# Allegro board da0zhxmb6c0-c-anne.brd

Outline 165.25 x 116 mm; copper layers: TOP, VCC, IN1, IN2, GND, BOTTOM. Coordinates in mm from the lower left corner of the outline.
Outline path: 0,35.15 0,9.05 4,9.05 arc(5.5,7.55) 4,6.05 2.8,6.05 2.8,1 arc(3.09,0.29) 3.8,0 6.81,0 arc(7.5,0.27) 7.81,0.94 arc(10.08,6.09) 15.17,8.47 arc(17.32,9.16) 18.95,10.71 19.1,10.95 arc(19.46,11.28) 19.94,11.4 24.09,11.4 arc(26,12.09) 27.04,13.85 arc(27.38,14.43) 28.02,14.66 30.85,14.66 arc(31.2,14.81) 31.35,15.16 31.35,17.7 arc(31.5,18.05) 31.85,18.2 35.85,18.2 arc(36.2,18.05) 36.35,17.7 36.35,15.16 arc(36.5,14.81) 36.85,14.66 51.32,14.66 arc(52.03,14.37) 52.32,13.66 52.32,13.6 59.8,13.6 arc(60.51,13.89) 60.8,14.6 103.02,14.6 arc(103.73,14.89) 104.02,15.6 104.02,17.4 arc(104.31,18.11) 105.02,18.4 154.5,18.4 arc(155.21,18.69) 155.5,19.4 155.5,28 arc(155.79,28.71) 156.5,29 156.6,29 arc(157.31,29.29) 157.6,30 157.6,78 arc(157.31,78.71) 156.6,79 152,79 arc(151.29,79.29) 151,80 151,89 arc(151.29,89.71) 152,90 165.25,90 165.25,92 161.64,92 arc(161.15,92.4) 161.44,92.96 161.44,112.04 arc(161.15,112.6) 161.64,113 165.25,113 165.25,114.5 135.2,114.5 arc(134.49,114.79) 134.2,115.5 134.2,116 115.3,116 115.3,114.95 arc(115.01,114.24) 114.3,113.95 101,113.95 arc(100.29,114.24) 100,114.95 100,116 86.5,116 arc(85.79,115.71) 85.5,115 85.5,108.5 arc(85.21,107.79) 84.5,107.5 60,107.5 arc(59.29,107.21) 59,106.5 59,104.5 arc(58.71,103.79) 58,103.5 21.7,103.5 arc(20.99,103.79) 20.7,104.5 20.7,105 arc(19.67,107.47) 17.2,108.5 7.7,108.5 arc(6.99,108.21) 6.7,107.5 6.7,106.3 arc(6.11,104.89) 4.7,104.3 3.6,104.3 arc(3.25,104.15) 3.1,103.8 3.1,101.6 arc(2.95,101.25) 2.6,101.1 2.1,101.1 arc(1.75,100.95) 1.6,100.6 1.6,98.85 11.7,98.85 arc(12.2,98.35) 11.7,97.85 11.7,92.85 arc(12.2,92.35) 11.7,91.85 1.6,91.85 1.6,89.25 arc(1.45,88.9) 1.1,88.75 0.9,88.75 0.9,86.75 7.5,86.75 arc(7.75,86.5) 7.5,86.25 7.5,71.75 arc(7.75,71.5) 7.5,71.25 0.9,71.25 0.9,69.25 1.65,69.25 arc(2,69.1) 2.15,68.75 2.15,66.1 9.95,66.1 arc(10.45,66.6) 10.95,66.1 10.95,52.4 arc(10.45,51.9) 9.95,52.4 2.15,52.4 2.15,47.2 12.35,47.2 arc(12.85,46.7) 12.35,46.2 12.35,40.65 arc(12.85,40.15) 12.35,39.65 2.15,39.65 2.15,37.95 2.95,37.95 arc(3.66,37.66) 3.95,36.95 3.95,36.15 arc(3.66,35.44) 2.95,35.15 0,35.15

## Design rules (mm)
constraint set DEFAULT: min track width 0.108
net group W4(5.5)-2B: nets SOC_CLKOUT_0 SOC_CLKOUT_1
net group W25-T12B: nets RING2 SLEEVE
net group DFP-S4(5)W4(5.5)-2B: nets USB30_RX0+ USB30_RX0+_R USB30_RX0- USB30_RX0-_R USB30_TX0+ USB30_TX0+_C USB30_TX0+_R USB30_TX0- USB30_TX0-_C USB30_TX0-_R
net group DFP-S4(5)W4(5.5)-12B: nets PCIE_RXN2_WLAN PCIE_RXP2_WLAN PCIE_TXN2_WLAN PCIE_TXP2_WLAN
net group DFP-S4(5)W4(5.5)-T2B: nets 5V_HSMBCK 5V_HSMBDT HDMI_SCLK HDMI_SDATA PCIE_TXN2_WLAN_C PCIE_TXP2_WLAN_C SDVO_CLK SDVO_DATA SOC_PCIE_COMN SOC_PCIE_COMP
net group DFP-S4(5)W4(5.5)-T12B: nets CLK_PCIE_WLANN CLK_PCIE_WLANP SATA_RCOMP_DN SATA_RCOMP_DP SATA_RXN0_NGFF SATA_RXN0_R SATA_RXP0_NGFF SATA_RXP0_R SATA_TXN0_NGFF SATA_TXN0_R SATA_TXP0_NGFF SATA_TXP0_R TS_USB+ TS_USB+_I2CCL TS_USB- TS_USB-_I2CDA USB_CAR_N USB_CAR_P USB_CR_N USB_CR_P USB_HUB_N USB_HUB_P USBP0+ USBP0+_R USBP0- USBP0-_R USBP1+ USBP1- USBP2+ USBP2- USBP2_CAR_N USBP2_CAR_P USBP3+ USBP3+_R USBP3- USBP3-_R USBP4+ USBP4-
net group DFP-S4.5(4)W5.5(6)-T12B: nets M_A_CLKN0 M_A_CLKP0 M_A_DQSN0 M_A_DQSN1 M_A_DQSN2 M_A_DQSN3 M_A_DQSN4 M_A_DQSN5 M_A_DQSN6 M_A_DQSN7 M_A_DQSP0 M_A_DQSP1 M_A_DQSP2 M_A_DQSP3 M_A_DQSP4 M_A_DQSP5 M_A_DQSP6 M_A_DQSP7 M_B_CLKN0 M_B_CLKP0 M_B_DQSN0 M_B_DQSN1 M_B_DQSN2 M_B_DQSN3 M_B_DQSN4 M_B_DQSN5 M_B_DQSN6 M_B_DQSN7 M_B_DQSP0 M_B_DQSP1 M_B_DQSP2 M_B_DQSP3 M_B_DQSP4 M_B_DQSP5 M_B_DQSP6 M_B_DQSP7
net group DFP-S6(4)W4.5(4)-T2B: nets C_TX0_HDMI+ C_TX0_HDMI- C_TX1_HDMI+ C_TX1_HDMI- C_TX2_HDMI+ C_TX2_HDMI- C_TXC_HDMI+ C_TXC_HDMI- EDP_AUX#_C EDP_AUX_C EDP_TX0#_C EDP_TX0_C EDP_TX1#_C EDP_TX1_C IN_CLK IN_CLK# IN_D0 IN_D0# IN_D1 IN_D1# IN_D2 IN_D2# INT_EDP_AUXN INT_EDP_AUXP INT_EDP_TXN0 INT_EDP_TXN1 INT_EDP_TXP0 INT_EDP_TXP1 SOC_DDI1_RCOMP SOC_DDI1_RCOMP_P SOC_DDIO_RCOMP SOC_DDIO_RCOMP_P
net group W3.5(4.75)-T12B: nets M_A_DM0 M_A_DM1 M_A_DM2 M_A_DM3 M_A_DM4 M_A_DM5 M_A_DM6 M_A_DM7 M_A_DQ0 M_A_DQ1 M_A_DQ2 M_A_DQ3 M_A_DQ4 M_A_DQ5 M_A_DQ6 M_A_DQ7 M_A_DQ8 M_A_DQ9 M_A_DQ10 M_A_DQ11 M_A_DQ12 M_A_DQ13 M_A_DQ14 M_A_DQ15 M_A_DQ16 M_A_DQ17 M_A_DQ18 M_A_DQ19 M_A_DQ20 M_A_DQ21 M_A_DQ22 M_A_DQ23 M_A_DQ24 M_A_DQ25 M_A_DQ26 M_A_DQ27 M_A_DQ28 M_A_DQ29 M_A_DQ30 M_A_DQ31 M_A_DQ32 M_A_DQ33 M_A_DQ34 M_A_DQ35 M_A_DQ36 M_A_DQ37 M_A_DQ38 M_A_DQ39 M_A_DQ40 M_A_DQ41 M_A_DQ42 M_A_DQ43 M_A_DQ44 M_A_DQ45 M_A_DQ46 M_A_DQ47 M_A_DQ48 M_A_DQ49 M_A_DQ50 M_A_DQ51 M_A_DQ52 M_A_DQ53 M_A_DQ54 M_A_DQ55 M_A_DQ56 M_A_DQ57 M_A_DQ58 M_A_DQ59 M_A_DQ60 M_A_DQ61 M_A_DQ62 M_A_DQ63 M_B_DM0 M_B_DM1 M_B_DM2 M_B_DM3 M_B_DM4 M_B_DM5 M_B_DM6 M_B_DM7 M_B_DQ0 M_B_DQ1 M_B_DQ2 M_B_DQ3 M_B_DQ4 M_B_DQ5 M_B_DQ6 M_B_DQ7 M_B_DQ8 M_B_DQ9 M_B_DQ10 M_B_DQ11 M_B_DQ12 M_B_DQ13 M_B_DQ14 M_B_DQ15 M_B_DQ16 M_B_DQ17 M_B_DQ18 M_B_DQ19 M_B_DQ20 M_B_DQ21 M_B_DQ22 M_B_DQ23 M_B_DQ24 M_B_DQ25 M_B_DQ26 M_B_DQ27 M_B_DQ28 M_B_DQ29 M_B_DQ30 M_B_DQ31 M_B_DQ32 M_B_DQ33 M_B_DQ34 M_B_DQ35 M_B_DQ36 M_B_DQ37 M_B_DQ38 M_B_DQ39 M_B_DQ40 M_B_DQ41 M_B_DQ42 M_B_DQ43 M_B_DQ44 M_B_DQ45 M_B_DQ46 M_B_DQ47 M_B_DQ48 M_B_DQ49 M_B_DQ50 M_B_DQ51 M_B_DQ52 M_B_DQ53 M_B_DQ54 M_B_DQ55 M_B_DQ56 M_B_DQ57 M_B_DQ58 M_B_DQ59 M_B_DQ60 M_B_DQ61 M_B_DQ62 M_B_DQ63
net group W4(5.5)-T2B: nets ACZ_BCLK ACZ_RST# ACZ_SDIN ACZ_SDOUT ACZ_SYNC CLK_24M_DEBUG CLK_24M_DEBUG_C CLK_TPM ICLK_ICOMP ICLK_RCOMP LPC_RCOMP PCH_AZ_CODEC_BITCLK PCH_AZ_CODEC_RST# PCH_AZ_CODEC_SDIN0 PCH_AZ_CODEC_SDOUT PCH_AZ_CODEC_SYNC RTC_X1 RTC_X2 SOC_GPIO_RCOMP SOC_PROCHOT# SVID_ALERT#_SOC SVID_CLK_SOC SVID_DATA_SOC XIN XOUT XTAL25_IN XTAL25_OUT
net group W4(5.5)-T12B: nets ACZ_SPKR BEEP_1 BRTC_EXTPAD CLK_24M_KBC CLKRUN# EMMC_CLK EMMC_CLK_R EMMC_CMD EMMC_DATA_0 EMMC_DATA_1 EMMC_DATA_2 EMMC_DATA_3 EMMC_DATA_4 EMMC_DATA_5 EMMC_DATA_6 EMMC_DATA_7 FST_SPI_D0 FST_SPI_D1 I2C_0_SCL I2C_0_SCL_C I2C_0_SDA I2C_0_SDA_C I2C_1_SCL I2C_1_SDA I2C_2_SCL I2C_2_SDA LAD0 LAD0_C LAD1 LAD1_C LAD2 LAD2_C LAD3 LAD3_C LFRAME# LFRAME#_C M_B_DRAMRST# PCBEEP PCBEEP_EC PCH_DISP_ON PCH_DISP_ON_C PCH_DPST_PWM PCH_DPST_PWM_C PCH_EDP_BLON PCH_EDP_BLON_C PLTRST# RSMRST# SCL_TO_EC SCL_TO_EC_R SD_CLK SD_CLK_R SD_CMD SD_CMD_R SD_D0 SD_D1 SD_D2 SD_D3 SD_DATA0_R SD_DATA1_R SD_DATA2_R SD_DATA3_R SDA_TO_EC SDA_TO_EC_R SLP_S4# SMB_SOC_CLK SMB_SOC_DATA SOC_CLKRUN# SOC_PLTRST# SOC_RSMRST# SOC_RTEST# SOC_SERIRQ SOC_SPI_CLK SOC_SPI_CLK_R SOC_SPI_CLK_R1 SOC_SPI_CS# SOC_SPI_CS#_R SOC_SPI_CS#_R1 SOC_SPI_MISO_R SOC_SPI_MISO_R1 SOC_SPI_MOSI_R SOC_SPI_MOSI_R1 SRT_CRST# SUSB# SUSC# TPCLK TPDATA VR_SVID_ALERT# VR_SVID_CLK VR_SVID_DATA
net group W4.5(6)-T12B: nets M_A_A0 M_A_A1 M_A_A2 M_A_A3 M_A_A4 M_A_A5 M_A_A6 M_A_A7 M_A_A8 M_A_A9 M_A_A10 M_A_A11 M_A_A12 M_A_A13 M_A_A14 M_A_A15 M_A_BS0 M_A_BS1 M_A_BS2 M_A_CAS# M_A_CKE0 M_A_CS#0 M_A_ODT0 M_A_RAS# M_A_WE# M_B_A0 M_B_A1 M_B_A2 M_B_A3 M_B_A4 M_B_A5 M_B_A6 M_B_A7 M_B_A8 M_B_A9 M_B_A10 M_B_A11 M_B_A12 M_B_A13 M_B_A14 M_B_A15 M_B_BS0 M_B_BS1 M_B_BS2 M_B_CAS# M_B_CKE0 M_B_CS#0 M_B_ODT0 M_B_RAS# M_B_WE#
net group W5-T2B: nets DMIC_CLK DMIC_CLK_R DMIC_DAT
net group W5-T12B: nets 2.469V 24737_CMPIN 24737_CMPOUT 24737_ILIM 51216PG AC_PROTECT ACIN ACPRESENT BATT_EN# BATT_EN#_R BI_GATE H_PROCHOT# HWPG_1.05V_EC# HWPG_1.35V MAINON N21102302 N21102373 NB670PG NB671EN NB671PG PCH_SUSPWRDANCK PMU_RSMRST# S5_ON SB_ACDC SUSON SUSPWRDANCK_EC SYS_HWPG SYS_SHDN# TEMP_MBAT VCORE_PWRGD VGG_PWRGD VR_READY_VCORE VR_READY_VGG VRON_VCORE VRON_VGG
net group W6.5(8.5)-T12B: nets M_A_DRAMRST#
net group W10-T1B: nets 24737_SRP
net group W10-T12B: nets 24737_ACDET 24737_ACN 24737_ACP 24737_BM# 24737_SRN 51216MODE 51216REFIN 51216S3 51216S5 51216TRIP 51216VDDQSNS +1.8VREF +1.35VSUS +3V_MINI1_VDD +3V_RTC +15V +V_SMDDR_VREF_DIMM +V_SMDDR_VREF_DQ0 +V_SMDDR_VREF_DQ1 COMP_VCORE COMP_VGG D/C# DDR_1P05_PWR DRAM_RCOMP0 DRAM_RCOMP1 FB_VCORE FB_VGG FUSE1_1P05_PWR FUSE3_1P05_PWR FUSE_1P05_PWR ICLK_1P05_PWR ICMNT ISEN1N_VCORE ISEN1N_VGG ISEN1P_VCORE ISEN1P_VGG M_A_VREF_CA M_A_VREF_DQ M_B_VREF_CA M_B_VREF_DQ MAIND MAINON_ON_G MBCLK MBDATA NB670CLK NB670EN NB671FB S5D SET1_VCORE SET1_VGG SET2_VCORE SET2_VGG SET3_VCORE SET3_VGG SETGND_VCORE SETGND_VGG TON_VCORE TON_VGG TSEN_VCORE TSEN_VGG USB_HSIC_RCOMP USBSSIC_1P05_PWR VCC0_SENSEN_R VCC0_SENSEP_R VCC1_SENSEN VCC1_SENSEN_R VCC1_SENSEP VCC1_SENSEP_R VCLK_VCORE VCLK_VGG VDIO_VCORE VDIO_VGG VGG_SENSEN VGG_SENSEN_R VGG_SENSEP VGG_SENSEP_R WRST#
net group W15-T12B: nets HPL HPL-1 HPL_SYS HPR HPR-1 HPR_SYS LINE1-L LINE1-R LINE1-VREFO-L LINE1-VREFO-R MIC2-VREFO RING2_R SLEEVE_R USB_RCOMP
net group W20-T12B: nets 5041_VCC 24737_BST 24737_REGN 24737_VCC 51216VBST 51216VBST_S +3V_LDO +3VPCU_EC BOOT_VCORE BOOT_VGG CCD_PWR DDI_1P15_PWR HDMI_5V NB670BST NB670BST_S NB670ENLDO NB671BST NB671BST_S PVCC_VCORE VCC_VCORE VCCRTC_1 VL
net group W30-T12B: nets 24737_DH 24737_DL 51216DRVH 51216DRVL +5V_HDD CORE_V1P15_PWR LGATE_VCORE LGATE_VGG
net group W35-T12B: nets L_SPK+ L_SPK+_1 L_SPK- L_SPK-_1 R_SPK+ R_SPK+_1 R_SPK- R_SPK-_1
net group W40-T12B: nets +1.15V +5VA BMPD_1P05_PWR
net group W60-T12B: nets +VDDQ_VTT CORE_1P05_PWR V_BLIGHT
net group W80-T12B: nets +LCDVCC
net group W99-T12B: nets 5VUSB_0

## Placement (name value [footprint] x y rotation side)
C1  470p/50v_4  [C0402]  15.97 63.05 90 bottom
C2  0.1u/10v_4  [C0402]  16.98 63.05 90 bottom
C3  0.1u/10v_4  [C0402]  150.1 103.54 270 bottom
C4  0.1u/10v_4  [C0402]  15.62 78.67 0 bottom
C5  0.1u/10v_4  [C0402]  15.62 79.69 0 bottom
C6  0.1u/10v_4  [C0402]  15.62 80.71 0 bottom
C7  0.1u/10v_4  [C0402]  15.62 81.72 0 bottom
C8  0.1u/10v_4  [C0402]  15.62 74.61 0 bottom
C9  0.1u/10v_4  [C0402]  15.62 75.63 0 bottom
C10  0.1u/10v_4  [C0402]  15.62 76.64 0 bottom
C11  0.1u/10v_4  [C0402]  15.62 77.66 0 bottom
C12  chb@1u/6.3v_4  [C0402]  88.34 37.79 270 bottom
C13  1u/6.3v_4  [C0402]  53.08 43.73 90 bottom
C14  100u/6.3v_1206  [C1206]  20.32 62.91 0 bottom
C15  4.7u/10v_6  [C0603]  154.71 108.04 180 bottom
C16  100u/6.3v_1206  [C1206]  151.69 104.95 90 bottom
C17  1u/10v_6  [C0603]  154.29 107.05 0 top
C18  10u/6.3v_6  [C0603]  42.76 36.11 180 bottom
C19  chb@10u/6.3v_6  [C0603]  68.9 36.54 0 bottom
C20  0.1u/10v_4  [C0402]  18.06 59.76 0 bottom
C21  0.1u/10v_4  [C0402]  18.06 60.77 0 bottom
C22  0.1u/10v_4  [C0402]  16.51 50.56 90 top
C23  0_4  [C0402]  10.03 32.86 180 top
C24  100p/50v_4  [C0402]  17.15 49.37 180 bottom
C25  4.7u/6.3v_6  [C0603]  17.53 45.94 0 bottom
C26  10u/6.3v_4  [C0402]  8.43 23.17 0 top
C27  100p/50v_4  [C0402]  15.86 39.44 180 bottom
C28  4.7u/6.3v_6  [C0603]  17.53 44.38 0 bottom
C30  *100p/50v_4  [C0402]  13.66 23.33 270 top
C31  0.1u/10v_4  [C0402]  3.31 22.08 0 top
C32  10u/6.3v_4  [C0402]  3.31 23.04 0 top
C33  *0.1u/10v_4  [C0402]  58.92 88.71 0 bottom
C34  0.1u/10v_4  [C0402]  13.27 21.49 180 top
C35  10u/6.3v_4  [C0402]  14.24 19.95 270 top
C36  10u/6.3v_4  [C0402]  3.31 21.13 0 top
C38  0.1u/10v_4  [C0402]  13.29 19.95 270 top
C39  0.1u/10v_4  [C0402]  66.92 85.5 180 bottom
C40  0.1u/10v_4  [C0402]  66.9 86.55 180 bottom
C41  *0.1u/10v_4  [C0402]  157.85 110.06 180 top
C42  1u/6.3v_4  [C0402]  143.89 98.77 180 top
C43  1u/10v_4  [C0402]  75.69 86.58 180 bottom
C44  1u/6.3v_4  [C0402]  145.67 98.77 0 top
C45  2.2u/6.3v_4  [C0402]  3.31 18.59 180 top
C47  chb@0.047u/10v_4  [C0402]  107.08 43.09 90 top
C48  1u/6.3v_4  [C0402]  56.42 35.65 90 bottom
C49  10u/6.3v_4  [C0402]  13.67 18.62 180 top
C50  *22p/50v_4  [C0402]  15.88 18.65 180 top
C51  *0.1u/10v_4  [C0402]  86.97 90.11 90 bottom
C52  1u/10v_4  [C0402]  3.51 15.99 0 top
C53  0.1u/10v_4  [C0402]  13.41 15.3 90 top
C55  10p/50v_4  [C0402]  15.88 16.81 0 top
C56  10u/6.3v_6  [C0603]  15.16 15.47 180 top
C57  1u/10v_4  [C0402]  3.51 14.85 180 top
C58  10u/6.3v_4  [C0402]  4.83 14.06 90 top
C59  0.1u/10v_4  [C0402]  119.64 86.2 0 bottom
C60  0_4  [C0402]  3.43 13.3 180 top
C61  0.1u/10v_4  [C0402]  10.54 11.5 90 top
C62  10u/6.3v_4  [C0402]  3.86 11.95 270 top
C63  0.1u/10v_4  [C0402]  68.58 93.03 90 bottom
C64  10u/6.3v_4  [C0402]  11.49 11.5 90 top
C65  0.1u/10v_4  [C0402]  6.12 12.22 0 top
C67  10u/6.3v_4  [C0402]  8.63 11.5 90 top
C68  0.1u/10v_4  [C0402]  9.59 11.5 90 top
C69  10u/6.3v_4  [C0402]  6.12 11.27 0 top
C70  0.1u/10v_4  [C0402]  69.6 93.03 90 bottom
C71  1000p/50v_4  [C0402]  68.45 98.9 0 top
C73  *10p/50v_4  [C0402]  68.45 97.88 180 top
C74  1000p/50v_4  [C0402]  65.15 99 180 top
C75  ac@1u/6.3v_4  [C0402]  150.24 99.91 270 top
C76  *1u/10v_4  [C0402]  15.37 31.71 0 top
C78  *10p/50v_4  [C0402]  65.15 97.98 0 top
C79  0.1u/10v_4x  [C0402]  72.54 93.36 270 bottom
C80  0.1u/10v_4x  [C0402]  73.64 93.36 270 bottom
C81  10u/6.3v_4  [C0402]  14.66 12.87 180 top
C83  0.1u/10v_4  [C0402]  14.66 11.91 180 top
C86  0.1u/10v_4  [C0402]  48.01 72.35 180 bottom
C90  1u/6.3v_4  [C0402]  45.76 89.73 180 bottom
C91  tpm@10u/6.3v_6  [C0603]  127.26 75.53 270 bottom
C92  tpm_n@0.1u/10v_4  [C0402]  140.83 76.04 90 bottom
C94  tpm_n@10u/6.3v_6  [C0603]  139.67 75.91 270 bottom
C95  tpm@0.1u/10v_4  [C0402]  128.53 75.4 270 bottom
C97  tpm@0.1u/10v_4  [C0402]  129.29 71.47 90 bottom
C98  tpm@0.1u/10v_4  [C0402]  139.45 70.15 90 bottom
C99  tpm@0.1u/10v_4  [C0402]  140.4 70.15 90 bottom
C100  0.1u/10v_4  [C0402]  132.87 42.22 270 bottom
C101  0.01u/16v_4  [C0402]  100.48 65.54 90 bottom
C104  0.1u/10v_4  [C0402]  130.22 40.5 180 bottom
C108  *hd@100u/6.3v_3528  [C3528]  138.81 65.75 270 bottom
C117  *10p/50v_4  [C0402]  129.57 36.41 270 bottom
C118  0.1u/10v_4  [C0402]  142.98 28.01 90 bottom
C119  hd@0.01u/16v_4  [C0402]  146.58 76.7 0 bottom
C120  hd@0.01u/16v_4  [C0402]  146.58 77.65 0 bottom
C121  10u/6.3v_6  [C0603]  145.75 29.73 180 bottom
C122  hd@0.01u/16v_4  [C0402]  146.58 74.79 0 bottom
C123  hd@0.01u/16v_4  [C0402]  146.58 75.75 0 bottom
C124  0.1u/10v_4  [C0402]  134.34 22 0 top
C125  *0.1u/25v_4  [C0402]  150.6 27.93 270 top
C126  *0.1u/16v_4  [C0402]  149.1 42.38 270 top
C128  1000p/50v_6  [C0603]  35.28 26.84 0 top
C129  1000p/50v_6  [C0603]  35.28 25.06 0 top
C130  1000p/50v_6  [C0603]  35.28 23.41 0 top
C131  1000p/50v_6  [C0603]  35.28 21.63 0 top
C132  *0.1u/10v_4  [C0402]  155.2 92.93 270 top
C133  0.1u/10v_4x  [C0402]  156.21 92.93 270 top
C134  *220p/50v_4  [C0402]  16.13 83.25 90 top
C135  220p/50v_4  [C0402]  14.99 83.88 90 bottom
C138  15p/50v_4  [C0402]  69.2 86.74 0 bottom
C139  15p/50v_4  [C0402]  70.98 86.74 180 bottom
C140  15p/50v_4  [C0402]  72.63 88.13 180 bottom
C141  18p/50v_4  [C0402]  74.41 88.13 0 bottom
C142  0.1u/10v_4  [C0402]  77.85 83.89 180 top
C143  22u/6.3vs_6  [C0603]  93.46 62.03 180 top
C144  22u/6.3vs_6  [C0603]  63.37 91.51 90 top
C145  22u/6.3vs_6  [C0603]  79.16 93.21 0 top
C146  22u/6.3vs_6  [C0603]  59.95 91.46 90 top
C147  22u/6.3vs_6  [C0603]  64.9 91.51 90 top
C148  22u/6.3vs_6  [C0603]  79.19 90.22 0 top
C149  1u/10v_4  [C0402]  65.15 74.64 270 top
C150  0.1u/10v_4  [C0402]  82.91 83.75 0 top
C151  1u/10v_4  [C0402]  71.5 78.8 180 top
C152  1u/10v_4  [C0402]  66.42 76.42 270 top
C153  1u/10v_4  [C0402]  61.32 77.77 90 top
C154  1u/10v_4  [C0402]  71.5 77.82 180 top
C155  1u/10v_4  [C0402]  75.45 81.83 180 top
C156  1u/10v_4  [C0402]  64.01 74.64 270 top
C157  1u/10v_4  [C0402]  55.12 84.55 180 top
C158  1u/10v_4  [C0402]  66.4 86.02 270 top
C159  1u/10v_4  [C0402]  81.75 82.12 0 top
C160  1u/10v_4  [C0402]  77.59 85.18 0 top
C161  1u/10v_4  [C0402]  87.42 80.73 90 top
C162  1u/10v_4  [C0402]  60.05 78.15 90 top
C163  1u/10v_4  [C0402]  75.11 74.62 0 top
C164  1u/10v_4  [C0402]  75.09 79.67 180 top
C165  1u/10v_4  [C0402]  72.01 73.75 0 top
C166  1u/10v_4  [C0402]  71.14 75.45 90 top
C167  1u/10v_4  [C0402]  87.38 80.17 270 bottom
C168  0.1u/10v_4  [C0402]  83.61 81.77 0 top
C169  1u/10v_4  [C0402]  86.41 80.73 90 top
C170  1u/10v_4  [C0402]  84 80.38 90 top
C171  10u/6.3v_6x  [C0603]  157.73 106.74 90 top
C172  1u/10v_4  [C0402]  70.74 71.34 180 top
C173  0.1u/10v_4  [C0402]  78.93 82.17 180 top
C177  1u/10v_4  [C0402]  81.71 84.85 0 top
C178  1u/10v_4  [C0402]  56.92 77.48 180 top
C179  1u/10v_4  [C0402]  57.81 75.96 180 top
C180  1u/10v_4  [C0402]  70.14 74.89 90 top
C182  *0.1u/10v_4  [C0402]  45.98 68.54 180 bottom
C183  1u/10v_4  [C0402]  64.57 78.78 0 top
C188  22u/6.3vs_6  [C0603]  79.16 91.68 0 top
C191  1u/10v_4  [C0402]  67.82 76.42 180 top
C192  1u/10v_4  [C0402]  67.69 72.61 180 top
C193  1u/10v_4  [C0402]  85.08 79.56 90 top
C194  1u/10v_4  [C0402]  60.07 74.54 180 top
C195  1u/10v_4  [C0402]  66.3 73.5 90 top
C196  1u/10v_4  [C0402]  64.42 88.2 90 bottom
C199  1u/10v_4  [C0402]  86.54 76.46 270 top
C200  1u/10v_4  [C0402]  87.72 77.74 270 top
C201  0.1u/50v_6  [C0603]  61.72 92.78 270 bottom
C202  0.01u/25v_4  [C0402]  63.32 93.26 90 bottom
C203  1u/10v_4  [C0402]  63.4 88.2 90 bottom
C204  1u/10v_4  [C0402]  77.83 73.37 90 top
C205  22u/6.3vs_6  [C0603]  95.54 62.28 270 top
C206  1u/10v_4  [C0402]  72.45 70.73 90 top
C207  1u/10v_4  [C0402]  73.36 72.28 270 top
C208  1u/10v_4  [C0402]  67.82 77.43 180 top
C209  1u/10v_4  [C0402]  68.89 74.77 90 top
C211  1u/10v_4  [C0402]  77.21 74.74 0 top
C213  *4.7u/25v_8  [C0805]  59.74 93.08 90 bottom
C214  1u/10v_4  [C0402]  74.42 73.62 180 top
C215  1u/10v_4  [C0402]  76.19 76.06 180 top
C216  1u/10v_4  [C0402]  76.71 71.85 180 top
C217  1u/10v_4  [C0402]  64.9 72.43 270 top
C218  1u/10v_4  [C0402]  72.01 72.73 180 top
C219  1u/10v_4  [C0402]  66.33 88.2 90 bottom
C220  1u/10v_4  [C0402]  76.07 72.74 0 top
C221  22uf/6.3vt_6  [C0603]  58.82 66.67 270 top
C222  4.7uf/6.3v_6  [C0603]  57.02 66.65 270 top
C223  22uf/6.3vt_6  [C0603]  51.83 66.54 270 top
C224  1u/10v_4  [C0402]  68.28 71.47 0 top
C225  0.01u/25v_4  [C0402]  59.99 90.39 90 bottom
C226  0.1u/10v_4  [C0402]  57.12 90.38 270 bottom
C227  1u/10v_4  [C0402]  74.04 70.7 0 top
C228  1u/10v_4  [C0402]  84 68.89 90 top
C229  22u/6.3v_6  [C0603]  77.12 70.07 90 top
C230  22u/6.3v_6  [C0603]  98.16 74.53 270 top
C231  *0.1u/10v_4  [C0402]  58.56 90.38 270 bottom
C232  22u/6.3v_8  [C0805]  66 91.11 180 bottom
C233  2.2u/10v_8  [C0805]  63.41 90.7 270 bottom
C234  1u/10v_4  [C0402]  61.22 66.27 180 top
C235  4.7uf/6.3v_6  [C0603]  58.68 71.85 90 top
C236  4.7uf/6.3v_6  [C0603]  60.07 68.65 0 top
C237  4.7uf/6.3v_6  [C0603]  72.01 68.93 0 top
C238  4.7uf/6.3v_6  [C0603]  57.02 71.85 90 top
C239  22uf/6.3vt_6  [C0603]  48.5 68.08 270 top
C240  *10p/50v_4  [C0402]  128.53 73.24 0 bottom
C241  22uf/6.3vt_6  [C0603]  46.7 71.04 180 top
C242  4.7uf/6.3v_6  [C0603]  68 69.64 90 top
C243  1u/10v_4  [C0402]  64.9 66.77 270 top
C244  1u/10v_4  [C0402]  64.9 68.54 90 top
C245  1u/10v_4  [C0402]  63.12 68.8 180 top
C247  1u/10v_4  [C0402]  95.66 66.3 0 top
C248  1u/10v_4  [C0402]  84.08 64.73 270 top
C249  1u/10v_4  [C0402]  70.23 68.39 90 top
C250  1u/10v_4  [C0402]  75.69 68.67 270 top
C251  1u/10v_4  [C0402]  69.39 70.12 90 top
C252  22u/6.3v_6  [C0603]  89.89 72.93 270 top
C253  22u/6.3v_6  [C0603]  91.16 72.93 270 top
C254  22u/6.3v_6  [C0603]  92.43 72.93 270 top
C255  1u/10v_4  [C0402]  63.12 66.37 180 top
C256  1u/10v_4  [C0402]  92.12 76.8 180 top
C257  22uf/6.3vt_6  [C0603]  98.44 57.4 90 top
C258  gs@0.1u/25v_4  [C0402]  114.43 59.15 0 top
C259  1u/10v_4  [C0402]  74.73 68.67 90 top
C260  1u/10v_4  [C0402]  73.76 68.67 90 top
C261  22u/6.3vs_6  [C0603]  85.68 64.46 270 top
C262  22u/6.3vs_6  [C0603]  75.2 64.1 270 top
C263  *1u/16v_4  [C0402]  71.5 67.27 180 top
C264  *1u/16v_4  [C0402]  73.28 67.27 180 top
C265  22uf/6.3vt_6  [C0603]  99.95 57.37 90 top
C266  22uf/6.3vt_6  [C0603]  94.76 58.67 0 top
C267  22uf/6.3vt_6  [C0603]  94.76 60.19 0 top
C268  1u/10v_4  [C0402]  71.38 65.57 90 top
C269  1u/10v_4  [C0402]  72.39 65.57 90 top
C270  *0.1u/16v_4  [C0402]  153.44 63.11 90 top
C271  22uf/6.3vt_6  [C0603]  73.31 50.59 180 bottom
C272  *0.1u/16v_4  [C0402]  154.05 65.5 270 top
C273  22uf/6.3vt_6  [C0603]  71.97 48.94 0 bottom
C274  0.01u/25v_4  [C0402]  152.02 63.08 90 top
C275  gs@0.1u/25v_4  [C0402]  115.66 52.67 270 top
C278  10u/6.3v_6  [C0603]  151.99 65.5 270 top
C279  0.1u/10v_4  [C0402]  137.8 39.97 270 bottom
C282  0.1u/10v_4  [C0402]  131.7 40.1 270 bottom
C283  0.1u/10v_4  [C0402]  136.15 36.76 270 bottom
C284  0.1u/10v_4  [C0402]  71.63 62.07 270 top
C286  0.1u/10v_4  [C0402]  108.71 39.08 90 bottom
C287  0.1u/10v_4  [C0402]  123.95 35.02 0 top
C288  0.1u/10v_4  [C0402]  142.29 37.68 90 bottom
C289  0.1u/10v_4  [C0402]  141.34 37.68 90 bottom
C290  1u/6.3v_4  [C0402]  123.95 32.98 0 top
C292  0.1u/10v_4  [C0402]  123.95 34 0 top
C294  1u/10v_6  [C0603]  144.07 100.88 180 top
C297  0.1u/10v_4  [C0402]  124.46 28.16 90 top
C314  gs@10u/6.3v_6  [C0603]  109.14 22.82 0 top
C315  em@0.1u/10v_4  [C0402]  116.21 80.99 0 top
C316  0.1u/25v_4  [C0402]  111.63 52.92 90 top
C317  *0.1u/10v_4  [C0402]  48.9 26.63 270 bottom
C318  *1000p/50v_4  [C0402]  49.79 26.63 90 bottom
C319  0.1u/25v_4  [C0402]  109.09 55.08 90 bottom
C320  180p/50v_4  [C0402]  42.8 19.01 180 top
C321  gs@0.1u/10v_4  [C0402]  109.35 25.74 0 top
C322  em@0.1u/10v_4  [C0402]  114.17 77.31 180 top
C323  *33p/50v_4  [C0402]  120.78 21.03 180 top
C324  0.1u/10v_4  [C0402]  48.01 24.48 270 bottom
C325  0.1u/10v_4  [C0402]  46.74 25.19 270 bottom
C326  *22p/50v_4  [C0402]  114.94 29.17 0 top
C327  em@0.1u/10v_4  [C0402]  120.02 76.29 270 top
C328  em@1u/6.3v_4  [C0402]  115.32 78.7 270 top
C329  10p/50v_4  [C0402]  45.59 18.38 270 top
C330  10p/50v_4  [C0402]  46.61 18.38 270 top
C331  em@0.1u/10v_4  [C0402]  119.64 78.45 90 top
C333  0.22u/25v_6  [C0603]  49.15 24.48 270 bottom
C334  em@1u/6.3v_4  [C0402]  121.03 77.94 0 top
C335  *33p/50v_4  [C0402]  120.27 23.89 180 top
C336  em@1u/6.3v_4  [C0402]  117.48 73.24 0 top
C337  em@1u/6.3v_4  [C0402]  119.38 73.75 180 top
C338  em@0.1u/10v_4  [C0402]  116.46 78.7 90 top
C339  em@0.1u/10v_4  [C0402]  116.97 75.02 270 top
C340  em@0.1u/10v_4  [C0402]  115.19 74.89 180 top
C419  0.1u/16v_4  [C0402]  19.79 24.65 180 bottom
C420  4.7u/6.3v_6  [C0603]  19.58 23.46 0 bottom
C423  1u/6.3v_4  [C0402]  30.35 28.67 0 bottom
C425  4.7u/6.3v_6  [C0603]  28.7 30.66 270 bottom
C426  0.1u/16v_4  [C0402]  27.69 30.71 270 bottom
C427  68p/50v_4  [C0402]  26.67 30.71 270 bottom
C438  1u/6.3v_4  [C0402]  21.97 27.27 180 bottom
C573  *0.1u/10v_4  [C0402]  142.01 108.15 270 top
C575  *0.1u/10v_4  [C0402]  140.61 106.16 180 top
C576  *1u/6.3v_4  [C0402]  144.04 104.89 0 top
C594  180p/50v_4  [C0402]  40.39 18.89 180 top
C595  180p/50v_4  [C0402]  153.85 96.87 180 top
C596  180p/50v_4  [C0402]  78.41 93.61 90 bottom
C597  180p/50v_4  [C0402]  158.12 101.44 90 top
C601  *ssd@10u/6.3v_6  [C0603]  153.02 54.53 90 top
C602  *ssd@0.01u/25v_4  [C0402]  154.88 57.51 270 top
C603  10u/6.3v_6  [C0603]  62.71 67.54 0 top
C604  22u/6.3v_6  [C0603]  93.79 72.96 270 top
C694  180p/50v_4  [C0402]  153.85 97.95 180 top
C698  180p/50v_4  [C0402]  70.87 98.52 90 top
C700  180p/50v_4  [C0402]  81.99 93.69 270 bottom
C702  *0.1u/10v_4  [C0402]  107.04 101.97 0 bottom
C703  1u/6.3v_4  [C0402]  70.94 47.73 90 top
C704  1u/6.3v_4  [C0402]  88.42 39.59 90 bottom
C705  1u/6.3v_4  [C0402]  56.37 38.12 0 bottom
C706  1u/6.3v_4  [C0402]  92.99 35.66 180 bottom
C707  1u/6.3v_4  [C0402]  50.39 34.02 0 top
C708  1u/6.3v_4  [C0402]  56.96 33.63 90 top
C709  1u/6.3v_4  [C0402]  59.71 33.14 180 top
C710  10u/6.3v_6  [C0603]  55.34 32.94 90 top
C711  *1u/6.3v_4  [C0402]  106.06 47.41 90 bottom
C712  *1u/6.3v_4  [C0402]  39.17 41.99 270 bottom
C713  1u/6.3v_4  [C0402]  55.88 48.17 90 bottom
C714  1u/6.3v_4  [C0402]  74.24 49.51 90 top
C715  1u/6.3v_4  [C0402]  74.09 42.7 90 top
C716  1u/6.3v_4  [C0402]  74.06 40.67 90 top
C717  1u/6.3v_4  [C0402]  84.34 36.95 180 top
C718  1u/6.3v_4  [C0402]  60.54 35.86 180 bottom
C719  0.1u/16v_4  [C0402]  36.97 41.95 180 bottom
C720  10u/6.3v_6  [C0603]  76.27 36.26 180 top
C721  10u/6.3v_6  [C0603]  38.86 53.39 270 top
C722  10u/6.3v_6  [C0603]  42.61 36.57 180 top
C723  10u/6.3v_6  [C0603]  53.92 52.34 0 bottom
C724  10u/6.3v_6  [C0603]  68.72 36.6 0 top
C725  *1u/6.3v_4  [C0402]  49.31 55.44 180 top
C726  1u/6.3v_4  [C0402]  50.05 55.39 0 bottom
C727  0.1u/16v_4  [C0402]  38.12 47.03 90 top
C728  1u/6.3v_4  [C0402]  70.97 40.22 90 top
C729  1u/6.3v_4  [C0402]  39.12 49.24 90 bottom
C730  1u/6.3v_4  [C0402]  70.92 51.19 270 top
C731  1u/6.3v_4  [C0402]  60.2 36.46 90 top
C732  0.047u/10v_4  [C0402]  39.06 44.4 90 top
C733  0.047u/10v_4  [C0402]  38.12 44.4 90 top
C734  0.047u/10v_4  [C0402]  70.97 44.96 90 top
C735  0.047u/10v_4  [C0402]  71.91 44.81 90 top
C736  1u/6.3v_4  [C0402]  49.08 36.42 0 top
C737  1u/6.3v_4  [C0402]  39.17 41.23 90 top
C738  1u/6.3v_4  [C0402]  39.17 49.05 90 top
C739  1u/6.3v_4  [C0402]  39.14 51.06 90 top
C740  1u/6.3v_4  [C0402]  53.65 54.78 180 bottom
C741  1u/6.3v_4  [C0402]  53.65 53.89 180 bottom
C742  1u/6.3v_4  [C0402]  39.12 51.15 90 bottom
C743  1u/6.3v_4  [C0402]  49.16 36.49 0 bottom
C744  1u/6.3v_4  [C0402]  39.11 47.03 270 bottom
C745  0.047u/10v_4  [C0402]  39.11 47.03 270 top
C746  0.047u/10v_4  [C0402]  53.17 47.56 270 bottom
C747  0.047u/10v_4  [C0402]  70.99 44.45 270 bottom
C748  0.047u/10v_4  [C0402]  71.61 46.5 180 top
C749  0.1u/10v_4  [C0402]  57 47 270 top
C750  0.2p/50v_4  [C0402]  56.44 48.98 180 top
C751  chb@1u/6.3v_4  [C0402]  95.82 55.39 180 top
C752  chb@1u/6.3v_4  [C0402]  98.44 55.66 0 bottom
C753  chb@1u/6.3v_4  [C0402]  95.71 55.63 180 bottom
C754  chb@1u/6.3v_4  [C0402]  94.08 55.4 0 top
C755  chb@1u/6.3v_4  [C0402]  106.02 39.83 90 top
C756  chb@1u/6.3v_4  [C0402]  106.04 40.27 90 bottom
C757  chb@1u/6.3v_4  [C0402]  106.51 41.5 180 bottom
C758  chb@1u/6.3v_4  [C0402]  74.09 39.66 90 bottom
C759  chb@1u/6.3v_4  [C0402]  88.63 51.61 180 bottom
C760  chb@1u/6.3v_4  [C0402]  97.67 55.37 180 top
C761  chb@1u/6.3v_4  [C0402]  88.21 50.02 270 bottom
C762  chb@1u/6.3v_4  [C0402]  104.68 55.47 180 top
C763  22uf/6.3v_6  [C0603]  108.13 37.54 0 bottom
C764  chb@0.047u/10v_4  [C0402]  74.12 42.78 90 bottom
C765  chb@0.047u/10v_4  [C0402]  105.99 43.01 90 bottom
C766  chb@0.047u/10v_4  [C0402]  106.04 43.08 90 top
C767  chb@10u/6.3v_6  [C0603]  103.69 36.16 180 bottom
C768  chb@10u/6.3v_6  [C0603]  106.4 37.23 270 top
C769  chb@1u/6.3v_4  [C0402]  96.38 35.74 0 bottom
C770  chb@10u/6.3v_6  [C0603]  71.98 49.47 90 top
C771  chb@10u/6.3v_6  [C0603]  73.89 37.53 270 bottom
C772  chb@10u/6.3v_6  [C0603]  108.13 36.18 0 bottom
C773  chb@0.047u/10v_4  [C0402]  92.05 46.59 270 bottom
C774  chb@0.047u/10v_4  [C0402]  74.27 47.07 270 top
C775  chb@0.047u/10v_4  [C0402]  105.99 45.65 270 top
C776  chb@0.047u/10v_4  [C0402]  106.07 45.65 270 bottom
C777  chb@1u/6.3v_4  [C0402]  59.75 34.13 180 top
C778  chb@1u/6.3v_4  [C0402]  59.72 35.12 180 top
C779  chb@1u/6.3v_4  [C0402]  88.73 42.87 180 top
C780  chb@1u/6.3v_4  [C0402]  87.4 33.9 90 top
C781  chb@1u/6.3v_4  [C0402]  91.6 33.66 90 top
C782  chb@10u/6.3v_6  [C0603]  89.41 33.72 0 top
C783  chb@1u/6.3v_4  [C0402]  93.41 33.66 90 top
C784  chb@1u/6.3v_4  [C0402]  94.78 33.68 90 top
C785  chb@1u/6.3v_4  [C0402]  91.97 50.53 270 bottom
C786  chb@1u/6.3v_4  [C0402]  97.38 35.36 90 top
C787  chb@1u/6.3v_4  [C0402]  85.31 36.82 0 bottom
C788  chb@1u/6.3v_4  [C0402]  74.34 46.92 270 bottom
C789  chb@1u/6.3v_4  [C0402]  74.34 48.69 270 bottom
C790  chb@1u/6.3v_4  [C0402]  70.97 42.1 90 bottom
C791  chb@1u/6.3v_4  [C0402]  56.84 49.28 270 bottom
C792  chb@1u/6.3v_4  [C0402]  93.98 55.62 0 bottom
C793  chb@0.1u/10v_4  [C0402]  91.07 48.31 270 bottom
C794  chb@0.2p/50v_4  [C0402]  88.51 47.91 270 bottom
C795  chb@0.1u/16v_4  [C0402]  108.72 45.18 0 bottom
C798  hub@10u/6.3v_4  [C0402]  30.99 68.93 0 bottom
C799  hub@0.1u/16v_4  [C0402]  32.26 61.43 0 top
C800  hub@0.1u/16v_4  [C0402]  28.14 61.28 90 top
C801  hub@1u/6.3v_4  [C0402]  30.13 61.28 90 top
C802  hub@1u/6.3v_4  [C0402]  29.13 61.28 90 top
C803  hub@0.1u/16v_4  [C0402]  30.99 67.91 0 bottom
C804  hub@0.1u/16v_4  [C0402]  27.15 61.28 90 top
C805  hub@0.1u/16v_4  [C0402]  23.88 67.78 0 bottom
C806  hub@22p/50v_4  [C0402]  28.2 59.27 0 bottom
C807  hub@22p/50v_4  [C0402]  29.97 59.27 180 bottom
C808  hub@1u/6.3v_4  [C0402]  23.88 61.69 180 bottom
C812  0.1u/10v_4x  [C0402]  71.55 93.03 270 bottom
C813  0.1u/10v_4x  [C0402]  70.66 93.03 270 bottom
C814  *2.7p/50v_4  [C0402]  18.76 21.24 270 top
C815  *2.7p/50v_4  [C0402]  19.92 21.25 270 bottom
C816  *2.7p/50v_4  [C0402]  19.18 26.1 180 bottom
C817  *2.7p/50v_4  [C0402]  19.6 31.97 180 bottom
C818  *2.7p/50v_4  [C0402]  19.6 30 180 bottom
C819  *2.7p/50v_4  [C0402]  19.78 21.24 270 top
C828  180p/50v_4  [C0402]  109.2 34.59 90 bottom
C829  m2_ssd@0.01u/16v_2  [C0201]  146.2 75.75 180 top
C830  m2_ssd@0.01u/16v_2  [C0201]  146.2 74.79 180 top
C831  m2_ssd@0.01u/16v_2  [C0201]  145.95 76.7 180 top
C832  m2_ssd@0.01u/16v_2  [C0201]  145.95 77.65 180 top
C839  *1000p/50v_4  [C0402]  59.54 95.67 0 top
C840  *0.1u/10v_4  [C0402]  57.3 99.99 0 top
C841  *1u/6.3v_4  [C0402]  57.3 98.97 0 top
C842  4.7u/10v_6  [C0603]  19.05 57.24 90 bottom
C859  *1u/6.3v_4  [C0402]  139.63 52.7 90 top
C860  *10u/6.3v_4  [C0402]  140.88 56.37 270 top
C861  0.1u/10v_4  [C0402]  109.6 50.13 0 top
C862  m2_ssd@0.1u/16v_4  [C0402]  153.93 57.51 270 top
C863  m2_ssd@10u/6.3v_6  [C0603]  154.51 54.56 90 top
C864  *1000p/50v_4  [C0402]  50.29 82.13 90 top
C865  *1000p/50v_4  [C0402]  147.59 53.51 270 top
C866  *1000p/50v_4  [C0402]  30.36 46.79 90 top
C867  *1000p/50v_4  [C0402]  27.43 59.15 0 top
C868  *1000p/50v_4  [C0402]  15.38 21.32 180 top
C869  *1000p/50v_4  [C0402]  48.98 60.56 180 top
C870  *1000p/50v_4  [C0402]  109.35 54.71 90 top
C871  *1000p/50v_4  [C0402]  73.28 35.52 270 top
C872  *1000p/50v_4  [C0402]  71.63 35.52 270 top
C873  *10p/50v_4  [C0402]  17.02 15.46 90 top
C874  hub@1u/6.3v_4  [C0402]  23.5 27.9 270 top
C875  0.1u/10v_4  [C0402]  116.51 111.65 90 bottom
C876  0.1u/10v_4  [C0402]  131.57 59.99 0 top
C877  0.1u/25v_4  [C0402]  111.1 35.35 270 top
C878  0.1u/25v_4  [C0402]  87.35 21.48 180 top
C879  22u/6.3v_6  [C0603]  3.79 24.25 0 top
C880  10u/6.3v_4  [C0402]  6.78 9.95 90 top
CN1  usb3.0 conn  [USB-53065-00902-001-9P-SMT]  4.5 59.25 90 bottom
CN2  hdmi conn  [HDMI-80103-1121-19P-LDV-SMT]  2.7 79 90 bottom
CN3  usb_conn  [AF712L-A2G1T-12P-L-SMT]  148.9 98.5 180 bottom
CN5  ngff@wlan_ngff conn(type 2230)  [NGFF-51749-0750P-105-75P-KE]  159.8 102.5 270 bottom
CN6  combojack_2sj3080-003111f  [PHJK-2SJ3080-088111F-6P]  7.55 43.5 90 bottom
CN7  rtc_socket  [ML1220-SMT]  131 107.5 135 top
CN9  hd@hdd conn  [SATA-C166FQ-12208-L-22P-R]  155.4 57.8 270 bottom
CN10  7300l40-100000-g4  [LVDS-107K40-100011-G2-40P-L]  71 97.7 0 bottom
CN11  kb_conn  [50584-0280N-V01-28P-L]  120.73 28.5 180 bottom
CN12  tp_cn  [88513-0801-8P-L]  46.6 21.9 180 bottom
CN13  power conn  [50281-0040N-001-4P-L]  33.85 20.23 180 bottom
CN16  sd-card  [SDCARD-156-2001902600-11P-SMT]  15.4 22 90 bottom
CN18  m2_ssd@ssd_ngff conn  [NGFF-APCI0018-P002A-75P-KB-SMT]  149.28 62 270 bottom
D2  5v/30v/0.2p_4  [C0402]  14.99 56.3 90 bottom
D3  5v/30v/0.2p_4  [C0402]  14.99 58.08 270 bottom
D5  *vport_6  [R0603]  154.69 108.55 0 top
D7  rb500v-40  [DSM]  18.04 35.91 90 top
D8  rb500v-40  [DSM]  19.81 35.91 90 top
D9  bas316  [DSM]  22.99 22.06 270 top
D10  *bas316  [DSM]  24.77 22.06 270 top
D11  *az5125-01j  [R0402]  14.86 83.25 90 top
D12  *vport_6  [R0603]  155.47 101.34 180 top
D13  rb500v-40  [DSM]  20.19 82.23 0 bottom
D14  rb500v-40  [DSM]  20.19 84.14 0 bottom
D15  rb500v-40  [DSM]  35.56 28.54 0 bottom
D16  sdmk0340l-7-f  [DSMV]  121.21 34.28 90 top
D17  bat54c  [SOT323_213-2_1-1_3-2N7002W]  144.27 102.71 0 top
D18  *rb500v-40  [DSM]  133.73 56.61 0 top
D19  *rb500v-40  [DSM]  133.73 50.89 0 top
D20  rb500v-40  [DSM]  133.73 52.8 0 top
D21  *rb500v-40  [DSM]  133.73 54.7 0 top
D22  em@rb500v-40  [DSM]  105.26 77.25 0 bottom
D23  5v/30v/0.2p_4  [C0402]  14.99 59.86 90 bottom
D24  5v/30v/0.2p_4  [C0402]  14.99 61.64 270 bottom
D25  5v/30v/0.2p_4  [C0402]  14.99 52.88 90 bottom
D26  5v/30v/0.2p_4  [C0402]  14.99 54.59 270 bottom
D27  5v/30v/0.2p_4  [C0402]  15.5 48.86 90 top
D28  5v/30v/0.2p_4  [C0402]  6.99 36.54 180 bottom
D29  *5v/0.2p_4  [C0402]  142.01 106.37 270 top
D30  *5v/0.2p_4  [C0402]  140.61 107.31 0 top
D42  *az5725  [C0402]  109.86 33.24 0 bottom
D43  5v/30v/0.2p_4  [C0402]  149.23 39.59 270 bottom
D44  *5v/30v/0.2p_4  [C0402]  78.84 73.37 270 top
G1  *short_ pad1  [R0603]  144.4 97.37 180 top
HOLE1  *h-o158x118d158x118n  [H-O158X118D158X118N]  9.71 106 0 top
HOLE2  *h-c276d110p2  [H-C276D110P2]  17.2 105 0 top
HOLE3  *h-c276d110p2  [H-C276D110P2]  32 100.8 0 top
HOLE4  *h-c142x118d142x118n  [H-C142X118D142X118N]  40 100.8 0 top
HOLE5  *spad-zxx-5  [SPAD-ZXX-5]  17.2 105 0 top
HOLE6  *h-zxx-6  [H-ZXX-6]  92 112 0 top
HOLE7  *h-tc276ic276bc315d110p2  [H-TC276IC276BC315D110P2]  148 112 0 top
HOLE8  *spad-s354np  [SPAD-S354NP]  148 111.5 180 top
HOLE9  *h-c118d118n  [H-C118D118N]  155 112 0 top
HOLE10  *h-zxx-2  [H-ZXX-2]  16.5 69 0 top
HOLE11  *h-zxx-1  [H-ZXX-1]  33.84 83.66 90 top
HOLE12  *h-zxx-13  [H-ZXX-13]  104.55 60.78 0 top
HOLE13  *h-zhx-1  [H-ZHX-1]  154.13 32.85 0 top
HOLE14  *h-tc276ic197bc315d142x134p2  [H-TC276IC197BC315D142X134P2]  23 15 0 top
HOLE15  *spad-c315  [SPAD-C315]  54.4 17.7 0 top
HOLE16  *spad-zhx-2  [SPAD-ZHX-2]  55.88 17.78 0 bottom
HOLE17  *spad-c315  [SPAD-C315]  137 82.73 180 bottom
HOLE18  *spad-c315  [SPAD-C315]  137 82.73 0 top
JP1  *short_3720  [SHORT3720]  119.2 94.4 270 bottom
JP2  *short_3720  [SHORT3720]  99.54 94.68 90 bottom
JP3  *short_3720  [SHORT3720]  99.47 109.67 90 bottom
JP5  *short_3720  [SHORT3720]  124.84 94.45 90 bottom
JP7  *short_3720  [SHORT3720]  140.21 110.15 0 bottom
JP8  *short_3720  [SHORT3720]  36.4 34.97 270 bottom
JP10  *short_3720  [SHORT3720]  129.92 98.97 90 bottom
JP11  *short_3720  [SHORT3720]  121.92 110.23 90 bottom
JP12  *short_3720  [SHORT3720]  26.54 80.74 0 bottom
L2  0_6  [R0603]  15.62 49.17 90 bottom
L3  0_6  [R0603]  15.62 41.3 270 bottom
L4  hcb2012kf220t60/6a/22ohm_8  [R0805]  10.23 27.58 0 top
L5  80ohm_100mhz  [R0402]  16.51 48.86 270 top
L6  80ohm_100mhz  [R0402]  6.99 35.02 180 top
L7  0_6  [R0603]  8.56 9.7 180 top
L8  hcb1608kf-601t20(600,2a)  [R0603]  11.58 13.02 0 top
L9  blm15ag121sn1d(120,500ma)_4  [R0402]  130.22 39.54 180 bottom
L10  blm15ag121sn1d(120,500ma)_4  [R0402]  142.95 26.69 0 bottom
L11  blm15ag121sn1d(120,500ma)_4  [R0402]  142.04 28.03 90 bottom
LED2  led_amber/blue  [LEDLTST-S326KGJRKT-3P-SMT]  4.7 3 90 top
MR1  och1691wad  [SOT23_123-2_8-1_9]  156 104.5 270 top
MR3  *hgdedm013a  [SENSOR-1_3X0_9-5-4P]  141.5 104.5 0 top
NOREF  -  []  27.23 38.65 0 top
NOREF#2  -  [unnamed#2]  9.18 7.42 0 top
NOREF#3  -  [unnamed#2]  148.98 21.92 0 top
NOREF#4  -  []  56.01 -19.72 0 top
NOREF#5  -  [unnamed#2]  11.75 88.31 0 top
NOREF#6  -  []  5.21 -61.88 0 top
NOREF#7  -  []  56.95 27.12 0 top
NOREF#8  -  []  103.43 72.96 180 bottom
NOREF#9  -  []  48.52 97.37 180 bottom
NOREF#10  -  [unnamed#2]  9.18 7.42 180 bottom
NOREF#11  -  [unnamed#2]  12.71 88.44 180 bottom
NOREF#12  -  [unnamed#2]  148.98 21.92 180 bottom
PC1  2200p/50v_6  [C0603]  7.88 102.38 90 bottom
PC2  22u/6.3v_6  [C0603]  103.53 92.37 90 bottom
PC3  22u/6.3v_6  [C0603]  105.54 92.93 180 bottom
PC4  22u/6.3v_6  [C0603]  99.54 98.21 270 bottom
PC5  0.1u/50v_6  [C0603]  6.48 102.38 90 bottom
PC6  10u/10v_8  [C0805]  112 95.44 90 bottom
PC7  10u/10v_8  [C0805]  113.93 95.44 90 bottom
PC8  10u/10v_8  [C0805]  115.86 95.44 90 bottom
PC9  *220u/2.5v_3528  [C3528]  95.66 97.07 270 bottom
PC10  0.1u/50v_6  [C0603]  16.33 90.62 270 top
PC11  2.2u/6.3v_6  [C0603]  115.44 97.75 180 bottom
PC12  22u/6.3v_6  [C0603]  101.07 98.21 270 bottom
PC13  22u/6.3v_6  [C0603]  102.16 92.37 90 bottom
PC14  2.2u/6.3v_6  [C0603]  118.39 100.42 180 bottom
PC15  22u/6.3v_6  [C0603]  99.98 102.59 0 bottom
PC16  22u/6.3v_6  [C0603]  99.98 106.72 0 bottom
PC17  22u/6.3v_6  [C0603]  99.98 105.32 0 bottom
PC18  1u/10v_4  [C0402]  117.98 101.56 180 bottom
PC19  4.7u/10v_6  [C0603]  118.42 102.73 180 bottom
PC20  0.1u/50v_6  [C0603]  119.76 42.48 0 bottom
PC21  10u/6.3v_6  [C0603]  118.4 104.1 180 bottom
PC22  10u/6.3v_6  [C0603]  116.43 106.32 270 bottom
PC23  10u/6.3v_6  [C0603]  118.4 105.48 180 bottom
PC24  0.47u/25v_6  [C0603]  46.43 63.8 0 bottom
PC25  22u/6.3v_8  [C0805]  52.96 81.37 270 bottom
PC26  22u/6.3v_6  [C0603]  123.57 88.79 0 bottom
PC27  22u/6.3v_6  [C0603]  123.57 90.16 0 bottom
PC28  22u/6.3v_6  [C0603]  123.57 87.42 0 bottom
PC29  0.1u/10v_4  [C0402]  46.31 82.92 180 bottom
PC30  0.1u/10v_4  [C0402]  123.67 85.89 0 bottom
PC31  22u/6.3v_6  [C0603]  123.57 91.51 0 bottom
PC32  0.1u/50v_6  [C0603]  138.07 93.3 0 top
PC33  10u/6.3v_6  [C0603]  138.18 93.89 0 bottom
PC34  *0.1u/10v_4  [C0402]  45.21 63.08 180 top
PC35  *0.1u/10v_4  [C0402]  137.26 92.73 180 bottom
PC37  *0.1u/10v_4  [C0402]  46.1 65.24 180 bottom
PC39  22u/6.3v_8  [C0805]  54.87 81.37 270 bottom
PC40  0.47u/6.3v_4  [C0402]  43.59 61.44 90 bottom
PC41  0.1u/25v_4  [C0402]  42.27 70.27 270 bottom
PC43  100p/50v_4  [C0402]  42.31 61.09 90 bottom
PC44  330u/2v_7343  [CC7343]  49.53 81.12 90 bottom
PC45  0.1u/25v_4  [C0402]  134.06 98.11 180 top
PC46  0.1u/25v_4  [C0402]  134.04 99 0 top
PC47  10u/25v_8  [C0805]  134.47 100.07 180 bottom
PC48  390p/50v_4  [C0402]  43.78 57.94 0 top
PC49  *150u/6.3v_3528  [C3528]  125.5 111.09 270 bottom
PC50  2.2u/6.3v_6  [C0603]  39.98 60.65 270 bottom
PC51  1u/6.3v_4  [C0402]  130.56 94.96 90 bottom
PC52  *0.1u/10v_4  [C0402]  130.18 96.26 180 top
PC53  0.1u/25v_4  [C0402]  130.2 93.18 180 bottom
PC54  0.1u/10v_4  [C0402]  34.29 65.37 180 bottom
PC55  0.1u/10v_4  [C0402]  121.19 101.44 0 bottom
PC56  0.1u/25v_4  [C0402]  34.24 68.39 180 bottom
PC57  22u/6.3v_6  [C0603]  121.54 103.98 0 bottom
PC58  22u/6.3v_6  [C0603]  121.53 102.6 0 bottom
PC59  330u/2v_7343  [CC7343]  113.92 61.81 270 bottom
PC60  0.1u/10v_4  [C0402]  35.61 59.05 90 bottom
PC61  22u/6.3v_6  [C0603]  121.54 107.13 0 bottom
PC62  22u/6.3v_6  [C0603]  121.54 105.55 0 bottom
PC63  10u/25v_8  [C0805]  134.41 61.05 90 bottom
PC64  10u/25v_8  [C0805]  31.37 74.13 270 bottom
PC65  2200p/50v_4  [C0402]  136.81 60.77 90 bottom
PC66  0.1u/25v_4  [C0402]  29.97 74.39 270 bottom
PC67  0.1u/25v_4x  [C0402]  130.63 109.26 90 bottom
PC68  0.1u/25v_4  [C0402]  120.13 57.08 270 top
PC69  1u/6.3v_4  [C0402]  133.02 109.26 90 bottom
PC70  0.47u/25v_6  [C0603]  118.11 52.56 180 top
PC71  *0.1u/10v_4  [C0402]  116.69 52.56 0 bottom
PC72  0.1u/10v_4  [C0402]  127.37 53.29 0 bottom
PC73  *0.1u/10v_4  [C0402]  136.16 109.84 0 bottom
PC74  2200p/50v_4  [C0402]  147.45 105.12 270 bottom
PC75  15u/25v_7343  [CC7343]  23.75 76.42 180 bottom
PC76  *0.1u/10v_4  [C0402]  118.49 49.49 0 top
PC77  10u/25v_8  [C0805]  145.92 105.37 90 bottom
PC78  0.1u/25v_4  [C0402]  98.56 24.65 270 bottom
PC79  0.1u/25v_4  [C0402]  99.52 24.65 270 bottom
PC80  0.1u/25v_4  [C0402]  99.08 25.97 0 bottom
PC81  *680p/50v_6  [C0603]  90.84 26.58 0 top
PC82  *10u/6.3v_6  [C0603]  35.97 50.99 180 bottom
PC83  68p/50v_4  [C0402]  120.52 48.22 90 bottom
PC84  1u/16v_6  [C0603]  93.52 26.58 180 top
PC85  0.1u/10v_4  [C0402]  35.54 46.41 0 bottom
PC86  10u/6.3v_6  [C0603]  35.97 49.6 180 bottom
PC87  0.22u/10v_4  [C0402]  35.54 48.31 0 bottom
PC88  15u/25v_7343  [CC7343]  140.46 103.52 270 bottom
PC89  390p/50v_4  [C0402]  122.43 46.44 270 bottom
PC90  0.1u/10v_4  [C0402]  34.19 46.68 90 bottom
PC91  10u/25v_8  [C0805]  60.2 29.05 270 bottom
PC92  10u/25v_8  [C0805]  76.33 29.17 270 bottom
PC93  0.01u/25v_4  [C0402]  96.78 29.68 90 bottom
PC94  10u/25v_8  [C0805]  97.06 23.26 270 bottom
PC95  2200p/50v_6  [C0603]  95.57 22.38 90 bottom
PC96  47n/50v_6  [C0603]  92.07 23.16 180 top
PC97  0.01u/25v_4  [C0402]  31.27 46.68 90 bottom
PC99  10u/25v_8  [C0805]  137.19 106.06 90 bottom
PC100  100p/50v_4  [C0402]  103.03 24.09 180 top
PC101  *0.1u/10v_4  [C0402]  31.88 53.69 270 top
PC102  *0.1u/10v_4  [C0402]  30.74 53.69 270 top
PC103  0.47u/25v_6  [C0603]  95.12 19.78 180 top
PC104  0.1u/50v_6  [C0603]  97.92 19.78 0 top
PC105  0.1u/25v_4  [C0402]  28.54 49.73 90 bottom
PC106  0.1u/25v_4  [C0402]  20.02 53.87 270 bottom
PC107  1u/6.3v_4  [C0402]  29.23 47.86 90 bottom
PC108  0.1u/50v_6  [C0603]  97.92 18 180 top
PC109  0.1u/50v_6  [C0603]  95.12 18 0 top
PC110  2200p/50v_6  [C0603]  78.11 29.05 90 bottom
PC111  2200p/50v_4  [C0402]  24.54 52.37 0 bottom
PC112  10u/25v_8  [C0805]  25.32 48.94 180 bottom
PC114  2.2u/6.3v_6  [C0603]  112.9 100.17 270 top
PC115  0.1u/50v_6  [C0603]  12.19 102.38 90 bottom
PC116  2.2u/6.3v_6  [C0603]  114.43 100.17 270 top
PC117  0.1u/50v_6  [C0603]  119.76 37.11 0 bottom
PC118  22u/6.3v_6  [C0603]  99.98 103.95 0 bottom
PC119  22u/6.3v_6  [C0603]  99.98 101.23 0 bottom
PC120  22u/6.3v_6  [C0603]  115.06 106.31 270 bottom
PC121  22u/6.3v_6  [C0603]  113.72 106.31 270 bottom
PC122  0.1u/50v_6  [C0603]  23.75 84.8 0 bottom
PC123  2200p/50v_6  [C0603]  23.75 83.28 180 bottom
PC124  10u/10v_8  [C0805]  112.52 109.51 270 bottom
PC125  10u/10v_8  [C0805]  114.55 109.54 270 bottom
PC126  10u/10v_8  [C0805]  110.56 109.51 270 bottom
PC127  *2200p/50v_4  [C0402]  98.55 96.87 270 top
PC128  0.1u/50v_6  [C0603]  144.4 93.28 0 top
PC129  *0.1u/25v_4  [C0402]  41.84 58.02 270 top
PC130  0.1u/50v_6  [C0603]  144.91 88.18 0 top
PC131  *22u/6.3v_8  [C0805]  29.62 34.71 270 bottom
PC132  0.1u/50v_6  [C0603]  138.07 91.91 0 top
PC133  0.1u/50v_6  [C0603]  144.91 89.54 0 top
PC134  0.1u/50v_6  [C0603]  138.07 89.73 0 top
PC135  *0.1u/10v_4  [C0402]  44.32 71.34 90 top
PC136  22u/6.3v_8  [C0805]  32.54 42.23 0 bottom
PC137  22u/6.3v_8  [C0805]  33.58 34.71 270 bottom
PC138  *2200p/50v_4  [C0402]  135.93 89.25 270 bottom
PC139  10u/25v_8  [C0805]  134.47 98.11 180 bottom
PC140  2200p/50v_4  [C0402]  134.04 97.12 0 top
PC141  2.2u/6.3v_6  [C0603]  38.79 69.94 180 bottom
PC142  *2.2n/50v_4  [C0402]  117.48 92.17 270 top
PC143  22u/6.3v_8  [C0805]  110.62 61.94 90 bottom
PC144  0.1u/10v_4  [C0402]  113.36 62.32 90 top
PC145  *2200p/50v_4  [C0402]  129.93 61.42 270 top
PC146  *2200p/50v_4  [C0402]  38.61 76.29 180 top
PC147  0.1u/10v_4  [C0402]  34.32 66.34 0 top
PC148  2200p/50v_4  [C0402]  28.96 74.39 270 bottom
PC149  10u/25v_8  [C0805]  132.49 61.05 90 bottom
PC150  10u/25v_8  [C0805]  33.28 74.13 270 bottom
PC151  0.1u/25v_4  [C0402]  135.85 60.77 90 bottom
PC152  2.2u/6.3v_6  [C0603]  123.19 57.5 90 top
PC153  0.1u/25v_4  [C0402]  129.38 56.35 0 top
PC154  *0.1u/10v_4  [C0402]  118.48 54.67 180 top
PC155  *2200p/50v_4  [C0402]  128.19 110.1 270 bottom
PC156  0.1u/10v_4  [C0402]  129.38 55.4 180 top
PC157  0.1u/25v_4  [C0402]  143.33 105.22 90 bottom
PC158  0.1u/25v_4  [C0402]  144.4 105.25 270 bottom
PC159  0.47u/6.3v_4  [C0402]  119.57 48.22 90 top
PC160  0.1u/10v_4  [C0402]  119.19 46.31 270 top
PC161  1u/6.3v_4  [C0402]  123.59 48.1 270 bottom
PC162  *0.1u/25v_4  [C0402]  122.43 46.44 90 top
PC163  *2.2n/50v_4  [C0402]  107.25 109.01 180 top
PC164  0.1u/25v_4  [C0402]  95.1 29.19 180 top
PC165  0.1u/50v_6  [C0603]  61.85 29.05 270 bottom
PC166  *100p/50v_4  [C0402]  66.04 29.17 90 bottom
PC167  *47p/50v_4  [C0402]  74.04 18.68 90 top
PC168  *47p/50v_4  [C0402]  69.42 18.68 90 top
PC169  10u/25v_8  [C0805]  25.27 50.92 180 bottom
PC170  0.1u/25v_4  [C0402]  24.54 53.25 0 bottom
PC171  *2200p/50v_4  [C0402]  25.77 46.35 90 top
PC172  0.1u/25v_4  [C0402]  54.36 93.94 270 bottom
PC173  22u/6.3v_8  [C0805]  32.54 40.27 0 bottom
PC174  0.1u/50v_6  [C0603]  27.94 33.75 270 bottom
PC175  *22u/6.3v_8  [C0805]  31.6 34.71 270 bottom
PC176  22u/6.3v_8  [C0805]  32.54 44.19 0 bottom
PC177  22u/6.3v_8  [C0805]  99.94 74.7 270 top
PD1  da2j10100l  [DSM]  113.79 34.38 180 top
PD2  rb500v-40  [DSM]  92.71 24.76 0 top
PD3  1n4148ws  [DSM]  20.19 86.07 0 bottom
PD4  p4smafj20a  [D-DO-214AC]  25.91 95.49 0 bottom
PD5  sv1040  [D-TO277_213-6_1X4_3]  26.72 90.82 180 bottom
PD6  1ps302  [UMT_213-3-1_3]  141.1 94.96 0 top
PD7  1ps302  [UMT_213-3-1_3]  141.1 91.91 0 top
PD8  1ps302  [UMT_213-3-1_3]  141.1 88.84 0 top
PD9  pdz5.6b  [DSM]  72.65 20.03 270 top
PD10  pdz5.6b  [DSM]  70.87 20.03 270 top
PJ1  power_jack  [DCJK-2DC3079-007111F-2P]  4.7 95.35 90 bottom
PJ2  c114f3-108a1-l_batt_conn  [50458-00801-V02-8P-L]  69.88 21.68 175 bottom
PL1  0.47uh_7x7x3  [CHOKE-PCMC063T-3R3MN-SMT]  106.38 97.07 180 bottom
PL2  1uh_7x7x3  [CHOKE-PCMC063T-3R3MN-SMT]  105.79 105.86 180 bottom
PL3  3.3uh_7x7x3  [CHOKE-PCMC063T-3R3MN-SMT]  129.44 89.37 180 bottom
PL4  0.33uh_7x7x3  [CHOKE-PCMC063T-R82MN-4P-SMT]  43.44 77.94 90 bottom
PL5  0.33uh_7x7x3  [CHOKE-PCMC063T-R82MN-4P-SMT]  121.03 62.7 180 bottom
PL6  3.3uh_7x7x3  [CHOKE-PCMC063T-3R3MN-SMT]  127.38 105.04 180 bottom
PL7  6.8uh_7x7x3  [CHOKE-PCMC063T-3R3MN-SMT]  85.95 23.31 0 bottom
PL8  1uh_7x7x3  [CHOKE-PCMC063T-3R3MN-SMT]  25.02 38.7 270 bottom
PQ1  imd2at108  [IMD]  19.89 90.87 270 top
PQ2  ao3404  [SOT23_213-3_3-2]  96.27 103.44 270 bottom
PQ3  2n7002k  [SOT23_213-3_3-2]  122.94 39.47 270 bottom
PQ4  mdv1528q  [WDFN5-3_05X3_05-65]  124.21 98.92 0 bottom
PQ6  aon6978  [POWER-5X6-1_27-7P]  128.4 62.83 90 bottom
PQ7  aon6978  [POWER-5X6-1_27-7P]  37.09 74.26 270 bottom
PQ8  aon7410  [WDFN5-3_05X3_05-65]  92.86 25.29 0 bottom
PQ9  aon7410  [WDFN5-3_05X3_05-65]  92.71 20.82 90 bottom
PQ10  aol1413  [SO-8FL-5P-OA]  80.39 22.06 0 top
PQ11  *2n7002k  [SOT23_213-3_3-2]  101.21 28.48 180 bottom
PQ12  2n7002k  [SOT23_213-3_3-2]  103.99 29.02 0 top
PQ13  aon7410  [WDFN5-3_05X3_05-65]  21.91 45.43 270 bottom
PQ14  aon7752  [WDFN5-3_05X3_05-65]  26.37 45.59 90 bottom
PQ15  tpca8109  [POWER-5X5-1_27-5P]  18.62 92.06 90 bottom
PQ16  2n7002k  [SOT23_213-3_3-2]  118.37 36.24 180 top
PQ17  mdv1528q  [WDFN5-3_05X3_05-65]  111.12 109.63 180 top
PQ18  2n7002k  [SOT23_213-3_3-2]  85.88 100.96 270 top
PQ20  2n7002k  [SOT23_213-3_3-2]  108.69 88.74 270 top
PQ21  ao3409  [SOT23_213-3_3-2]  118.37 39.97 180 top
PQ22  dtc144eu  [UMT_213-3-1_3]  121.59 102.25 180 top
PQ23  2n7002k  [SOT23_213-3_3-2]  96.27 96.74 270 top
PQ24  dtc144eua  [UMT_213-3-1_3]  113.67 36.92 180 top
PQ27  *2n7002k  [SOT23_213-3_3-2]  117.08 89.1 90 top
PQ29  mdv1528q  [WDFN5-3_05X3_05-65]  115.74 109.64 90 top
PQ30  *dtc144eu  [UMT_213-3-1_3]  119.28 84.8 270 top
PQ31  *2n7002k  [SOT23_213-3_3-2]  112.84 89.12 270 top
PQ32  *ao3404  [SOT23_213-3_3-2]  113.93 84.93 270 top
PQ33  2n7002k  [SOT23_213-3_3-2]  99.4 109.35 90 top
PQ34  2n7002k  [SOT23_213-3_3-2]  100.23 105.62 90 top
PQ35  dtc144eu  [UMT_213-3-1_3]  99.95 102.07 270 top
PQ36  2n7002dw  [SC70-2_1-65-6P]  97.1 29.97 90 top
PQ37  2n7002k  [SOT23_213-3_3-2]  57.41 27.78 180 bottom
PQ38  2n7002dw  [SC70-2_1-65-6P]  88.65 103.22 180 bottom
PQ39  2n7002dw  [SC70-2_1-65-6P]  88.65 100.42 180 bottom
PR1  220k_4  [R0402]  17.48 90.49 270 top
PR2  0_4  [R0402]  118.26 99.89 0 top
PR3  0_4  [R0402]  104.94 100.88 0 bottom
PR4  *0_4  [R0402]  107.07 100.88 180 bottom
PR5  220k_4  [R0402]  17.48 92.27 270 top
PR6  *10k/f_4  [R0402]  118.26 100.9 0 top
PR7  0_4  [R0402]  104.94 101.97 0 bottom
PR8  *0_4  [R0402]  109.14 101.97 180 bottom
PR9  0_4  [R0402]  118.21 101.87 0 top
PR10  *0/short_4  [S0402]  19.23 93.46 180 top
PR11  200k_6  [R0603]  119.16 39.08 90 bottom
PR12  0_6  [R0603]  119.76 41.11 180 bottom
PR13  200k/f_4  [R0402]  112.52 37.56 90 bottom
PR14  200k/f_4  [R0402]  112.52 39.97 90 bottom
PR15  1.47k/f_4  [R0402]  122.17 42.72 0 bottom
PR16  10k/f_4_3435ntc  [R0402]  53.09 87.34 0 bottom
PR17  1m_6  [R0603]  115.44 39.97 270 top
PR18  0_6  [R0603]  137.92 95.39 180 top
PR19  *0/short_4  [S0402]  38.96 81.8 270 bottom
PR20  160/f_4  [R0402]  48.77 63.21 270 bottom
PR21  180/f_4  [R0402]  44.88 66.26 180 top
PR22  *0/short_4  [S0402]  38.61 80.25 0 bottom
PR23  *0/short_4  [S0402]  45.21 64.1 180 top
PR24  0_4  [R0402]  137.52 96.05 180 bottom
PR25  680/f_4  [R0402]  44.83 66.21 180 bottom
PR26  10k/f_4_3435ntc  [R0402]  41.99 84.42 90 bottom
PR27  0_4  [R0402]  41.28 67.96 180 top
PR28  10k/f_4_3435ntc  [R0402]  119.84 58.22 90 bottom
PR29  0_4  [R0402]  41.28 61.09 90 bottom
PR30  0_4  [R0402]  43.16 59.58 0 bottom
PR31  2.2/f_6  [R0603]  40.97 71.21 90 bottom
PR32  0_4  [R0402]  41.83 58.64 0 bottom
PR33  10k/f_4  [R0402]  41.91 60.95 90 top
PR34  *330k/f_4  [R0402]  129.67 94.07 90 top
PR35  1/f_6  [R0603]  128.65 94.33 90 bottom
PR36  0_4  [R0402]  36.42 67.43 180 bottom
PR37  866k/f_4  [R0402]  36.42 68.39 180 bottom
PR38  *0/short_4  [S0402]  36.37 69.54 0 bottom
PR39  13k/f_4  [R0402]  38.84 60.96 270 top
PR40  301/f_4  [R0402]  37.72 61.05 270 bottom
PR41  432/f_4  [R0402]  37.26 62.63 0 top
PR42  16.9/f_4  [R0402]  36.42 66.46 0 bottom
PR43  0_4  [R0402]  130.18 96.26 180 bottom
PR44  200/f_4  [R0402]  36.42 67.44 180 top
PR45  100k/f_4_4250ntc  [R0402]  39.5 83.66 90 bottom
PR46  64.9k/f_4  [R0402]  37.69 60.09 270 top
PR47  22.6k/f_4  [R0402]  36.73 59.05 270 bottom
PR48  39.2k/f_4  [R0402]  37.25 61.53 180 top
PR49  100k/f_4  [R0402]  36.45 64.48 0 bottom
PR50  6.49k/f_4  [R0402]  32.8 66.72 90 bottom
PR51  2.2_4  [R0402]  34.34 68.52 180 top
PR52  10k/f_4  [R0402]  36.4 68.47 180 top
PR53  100k/f_4_4250ntc  [R0402]  124.44 57.78 90 bottom
PR54  *0_4  [R0402]  41.15 62.93 180 top
PR55  0_4  [R0402]  39.32 62.93 0 top
PR56  2.2/f_6  [R0603]  121.29 57.5 90 top
PR57  2.2_6  [R0603]  124.59 57.5 90 top
PR58  10k/f_4  [R0402]  126.57 58.25 0 top
PR59  1/f_6  [R0603]  131.85 109.69 270 bottom
PR60  *0/short_4  [S0402]  117.83 58.21 90 bottom
PR61  *0/short_4  [S0402]  118.85 58.21 90 bottom
PR62  200/f_4  [R0402]  129.38 54.33 0 top
PR63  180/f_4  [R0402]  118.24 56.86 0 bottom
PR64  0_4  [R0402]  122.63 55.12 0 bottom
PR65  0_4  [R0402]  126.57 57.3 0 top
PR66  0_4  [R0402]  137.14 108.65 0 bottom
PR67  0_4  [R0402]  135.55 102.51 180 bottom
PR68  82k/f_4  [R0402]  134.34 111.57 90 bottom
PR69  200/f_4  [R0402]  127.37 55.4 0 top
PR70  0_4  [R0402]  135.55 103.47 180 bottom
PR71  11k/f_4  [R0402]  134.47 109.26 270 bottom
PR72  160/f_4  [R0402]  118.48 52.56 0 bottom
PR73  0_4  [R0402]  127.37 54.36 0 top
PR74  680/f_4  [R0402]  118.48 53.72 0 bottom
PR75  10k/f_4  [R0402]  118.49 51.58 180 bottom
PR76  16.9/f_4  [R0402]  127.37 53.29 180 top
